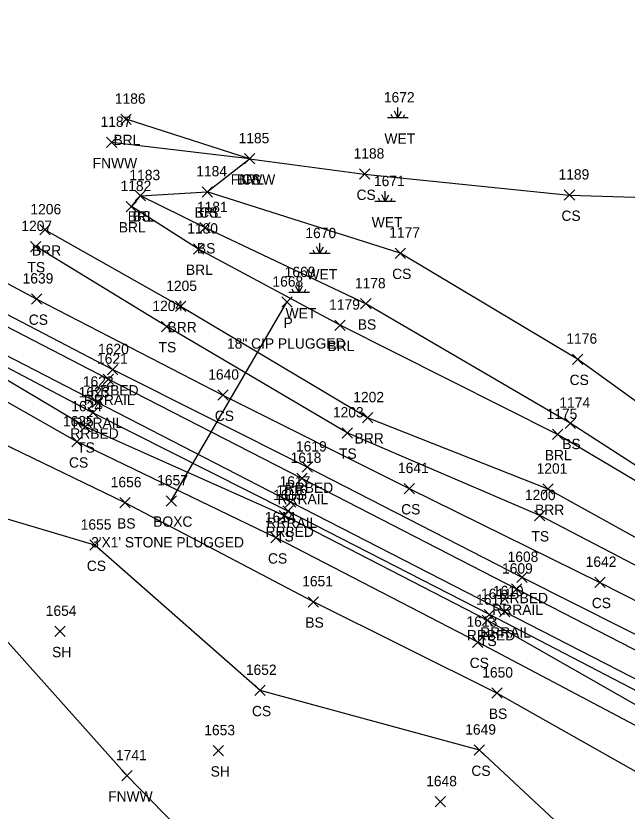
# Model space of a CAD drawing. Extents: x 1443960 to 1446865, y 610387 to 616706.
# Drawn here: x 1446375.4 to 1446493.6, y 611170.6 to 611324.5 of the extents above; entities that cross this region are included whole.
import ezdxf

# ---------------------------------------------------------------- set-up
doc = ezdxf.new("R2010")
doc.units = 0
for name, color, linetype in [('D_A', 7, 'Continuous'), ('D_C', 7, 'Continuous'), ('D_I', 7, 'Continuous'), ('D_TIC', 7, 'Continuous'), ('DCP', 7, 'Continuous'), ('L_A', 7, 'Continuous'), ('L_I', 7, 'Continuous'), ('L_TIC', 7, 'Continuous'), ('LABL', 7, 'Continuous'), ('LELB', 7, 'Continuous'), ('LFNC', 7, 'Continuous'), ('LWET', 7, 'Continuous'), ('R_A', 7, 'Continuous'), ('R_I', 7, 'Continuous'), ('R_TIC', 7, 'Continuous'), ('RR', 7, 'Continuous'), ('RRB', 7, 'Continuous')]:
    doc.layers.add(name, color=color, linetype=linetype)

msp = doc.modelspace()

# ---------------------------------------------------------------- linework, layer by layer
at = {"layer": 'D_TIC'}
for points in [[(1446426.77, 611268.12), (1446428.77, 611270.12)], [(1446428.77, 611268.12), (1446426.77, 611270.12)], [(1446404.42, 611229.65), (1446406.42, 611231.65)], [(1446406.42, 611229.65), (1446404.42, 611231.65)]]:
    msp.add_lwpolyline(points, dxfattribs=at)
at = {"layer": 'DCP'}
msp.add_lwpolyline([(1446405.42, 611230.65), (1446427.77, 611269.12)], dxfattribs=at)
at = {"layer": 'L_TIC'}
for points in [[(1446395.67, 611303.52), (1446397.67, 611305.52)], [(1446397.67, 611303.52), (1446395.67, 611305.52)], [(1446392.86, 611299.05), (1446394.86, 611301.05)], [(1446394.86, 611299.05), (1446392.86, 611301.05)], [(1446419.56, 611295.87), (1446421.56, 611297.87)], [(1446421.56, 611295.87), (1446419.56, 611297.87)], [(1446419.56, 611295.87), (1446421.56, 611297.87)], [(1446421.56, 611295.87), (1446419.56, 611297.87)], [(1446419.56, 611295.87), (1446421.56, 611297.87)], [(1446421.56, 611295.87), (1446419.56, 611297.87)], [(1446441.81, 611292.9), (1446443.81, 611294.9)], [(1446443.81, 611292.9), (1446441.81, 611294.9)], [(1446411.36, 611289.47), (1446413.36, 611291.47)], [(1446413.36, 611289.47), (1446411.36, 611291.47)], [(1446411.36, 611289.47), (1446413.36, 611291.47)], [(1446413.36, 611289.47), (1446411.36, 611291.47)], [(1446398.45, 611288.73), (1446400.45, 611290.73)], [(1446400.45, 611288.73), (1446398.45, 611290.73)], [(1446398.45, 611288.73), (1446400.45, 611290.73)], [(1446400.45, 611288.73), (1446398.45, 611290.73)], [(1446481.45, 611288.85), (1446483.45, 611290.85)], [(1446483.45, 611288.85), (1446481.45, 611290.85)], [(1446396.71, 611286.62), (1446398.71, 611288.62)], [(1446398.71, 611286.62), (1446396.71, 611288.62)], [(1446379.98, 611282.12), (1446381.98, 611284.12)], [(1446381.98, 611282.12), (1446379.98, 611284.12)], [(1446410.93, 611282.54), (1446412.93, 611284.54)], [(1446412.93, 611282.54), (1446410.93, 611284.54)], [(1446378.18, 611278.89), (1446380.18, 611280.89)], [(1446380.18, 611278.89), (1446378.18, 611280.89)], [(1446409.71, 611278.39), (1446411.71, 611280.39)], [(1446411.71, 611278.39), (1446409.71, 611280.39)], [(1446448.7, 611277.6), (1446450.7, 611279.6)], [(1446450.7, 611277.6), (1446448.7, 611279.6)], [(1446378.4, 611268.73), (1446380.4, 611270.73)], [(1446380.4, 611268.73), (1446378.4, 611270.73)], [(1446442.05, 611267.8), (1446444.05, 611269.8)], [(1446444.05, 611267.8), (1446442.05, 611269.8)], [(1446406.2, 611267.28), (1446408.2, 611269.28)], [(1446408.2, 611267.28), (1446406.2, 611269.28)], [(1446403.54, 611263.4), (1446405.54, 611265.4)], [(1446405.54, 611263.4), (1446403.54, 611265.4)], [(1446437.08, 611263.66), (1446439.08, 611265.66)], [(1446439.08, 611263.66), (1446437.08, 611265.66)], [(1446483.03, 611257.08), (1446485.03, 611259.08)], [(1446485.03, 611257.08), (1446483.03, 611259.08)], [(1446414.39, 611250.12), (1446416.39, 611252.12)], [(1446416.39, 611250.12), (1446414.39, 611252.12)], [(1446442.39, 611245.75), (1446444.39, 611247.75)], [(1446444.39, 611245.75), (1446442.39, 611247.75)], [(1446481.61, 611244.67), (1446483.61, 611246.67)], [(1446483.61, 611244.67), (1446481.61, 611246.67)], [(1446387.8, 611244), (1446389.8, 611246)], [(1446389.8, 611244), (1446387.8, 611246)], [(1446438.45, 611242.81), (1446440.45, 611244.81)], [(1446440.45, 611242.81), (1446438.45, 611244.81)], [(1446479.13, 611242.51), (1446481.13, 611244.51)], [(1446481.13, 611242.51), (1446479.13, 611244.51)], [(1446386.19, 611241.09), (1446388.19, 611243.09)], [(1446388.19, 611241.09), (1446386.19, 611243.09)], [(1446450.44, 611232.03), (1446452.44, 611234.03)], [(1446452.44, 611232.03), (1446450.44, 611234.03)], [(1446477.3, 611231.93), (1446479.3, 611233.93)], [(1446479.3, 611231.93), (1446477.3, 611233.93)], [(1446395.49, 611229.29), (1446397.49, 611231.29)], [(1446397.49, 611229.29), (1446395.49, 611231.29)], [(1446426.27, 611226.8), (1446428.27, 611228.8)], [(1446428.27, 611226.8), (1446426.27, 611228.8)], [(1446475.68, 611226.8), (1446477.68, 611228.8)], [(1446477.68, 611226.8), (1446475.68, 611228.8)], [(1446424.68, 611222.52), (1446426.68, 611224.52)], [(1446426.68, 611222.52), (1446424.68, 611224.52)], [(1446389.63, 611221.09), (1446391.63, 611223.09)], [(1446391.63, 611221.09), (1446389.63, 611223.09)], [(1446487.32, 611213.89), (1446489.32, 611215.89)], [(1446489.32, 611213.89), (1446487.32, 611215.89)], [(1446431.91, 611210.11), (1446433.91, 611212.11)], [(1446433.91, 611210.11), (1446431.91, 611212.11)], [(1446465.55, 611206.56), (1446467.55, 611208.56)], [(1446467.55, 611206.56), (1446465.55, 611208.56)], [(1446382.87, 611204.4), (1446384.87, 611206.4)], [(1446384.87, 611204.4), (1446382.87, 611206.4)], [(1446463.69, 611202.31), (1446465.69, 611204.31)], [(1446465.69, 611202.31), (1446463.69, 611204.31)], [(1446421.58, 611192.97), (1446423.58, 611194.97)], [(1446423.58, 611192.97), (1446421.58, 611194.97)], [(1446467.4, 611192.46), (1446469.4, 611194.46)], [(1446469.4, 611192.46), (1446467.4, 611194.46)], [(1446413.54, 611181.3), (1446415.54, 611183.3)], [(1446415.54, 611181.3), (1446413.54, 611183.3)], [(1446464.02, 611181.42), (1446466.02, 611183.42)], [(1446466.02, 611181.42), (1446464.02, 611183.42)], [(1446395.85, 611176.46), (1446397.85, 611178.46)], [(1446397.85, 611176.46), (1446395.85, 611178.46)], [(1446456.46, 611171.43), (1446458.46, 611173.43)], [(1446458.46, 611171.43), (1446456.46, 611173.43)]]:
    msp.add_lwpolyline(points, dxfattribs=at)
at = {"layer": 'LABL'}
for points in [[(1446517.97, 611221.87), (1446505.83, 611228.19), (1446480.13, 611243.51), (1446438.08, 611264.66), (1446410.71, 611279.39), (1446397.71, 611287.62), (1446399.45, 611289.73), (1446412.36, 611290.47), (1446420.56, 611296.87), (1446396.67, 611304.52)], [(1446517.97, 611221.87), (1446516.05, 611212), (1446478.3, 611232.93), (1446443.39, 611246.75), (1446407.2, 611268.28), (1446380.98, 611283.12)]]:
    msp.add_lwpolyline(points, dxfattribs=at)
at = {"layer": 'LELB'}
for points in [[(1446552.99, 611382.07), (1446558.67, 611362.69), (1446557.44, 611341.16), (1446560.67, 611304.99), (1446555.64, 611264.16), (1446556.53, 611215.55), (1446554.81, 611203.13), (1446541.6, 611207.37), (1446517.97, 611221.87), (1446506.75, 611230.08), (1446482.61, 611245.67), (1446443.05, 611268.8), (1446411.93, 611283.54), (1446399.45, 611289.73)], [(1446420.56, 611296.87), (1446442.81, 611293.9), (1446482.45, 611289.85), (1446511.86, 611288.91), (1446544.12, 611276.01)], [(1446554.81, 611203.13), (1446527.38, 611226.19), (1446501.38, 611245.5), (1446484.03, 611258.08), (1446449.7, 611278.6), (1446412.36, 611290.47)], [(1446344.24, 611288.47), (1446379.4, 611269.73), (1446415.39, 611251.12), (1446451.44, 611233.03), (1446488.32, 611214.89), (1446522.86, 611197.29), (1446554.41, 611180.54)], [(1446576.67, 611181), (1446566.72, 611186.09), (1446559.62, 611190.7), (1446541.15, 611196.83), (1446511.61, 611209.64), (1446476.68, 611227.8), (1446439.45, 611243.81), (1446404.54, 611264.4), (1446379.18, 611279.89)], [(1446548.85, 610888.19), (1446553.44, 610932.22), (1446554.61, 610954.43), (1446557.18, 610985.54), (1446561.83, 611026.07), (1446565.58, 611053.66), (1446570.69, 611096.92), (1446573.29, 611130.79), (1446568.51, 611145), (1446569.91, 611148.66), (1446564.88, 611156.7), (1446536.84, 611169.59), (1446508.69, 611183.48), (1446466.55, 611207.56), (1446427.27, 611227.8), (1446388.8, 611245), (1446349.69, 611268.25), (1446343.09, 611268.96)], [(1446552.43, 611156.81), (1446533.31, 611167.82), (1446507.38, 611180.73), (1446464.69, 611203.31), (1446425.68, 611223.52), (1446387.19, 611242.09), (1446349.13, 611263.69), (1446342.52, 611266.22)], [(1446545.33, 610990.77), (1446549.45, 611028.52), (1446549.03, 611055.59), (1446553.29, 611104.25), (1446542.01, 611115.66), (1446540.05, 611127.24), (1446544.04, 611129.96), (1446551.51, 611136.49), (1446553.27, 611138.91), (1446550.53, 611149.51), (1446533.12, 611159.93), (1446498.33, 611176.52), (1446468.4, 611193.46), (1446432.91, 611211.11), (1446396.49, 611230.29), (1446366.67, 611244.64), (1446348.43, 611256.48)], [(1446530.86, 610991.05), (1446536.61, 611027.8), (1446530.46, 611055.9), (1446528.01, 611097.29), (1446529.9, 611126.45), (1446531.13, 611139.44), (1446489.18, 611159.91), (1446465.02, 611182.42), (1446422.58, 611193.97), (1446390.63, 611222.09), (1446361.12, 611230.87), (1446345.74, 611242.49)]]:
    msp.add_lwpolyline(points, dxfattribs=at)
at = {"layer": 'LFNC'}
for points in [[(1446420.56, 611296.87), (1446393.86, 611300.05)], [(1446365.2, 611212.86), (1446396.85, 611177.46)], [(1446487.06, 611083.87), (1446458.93, 611112.28), (1446429.85, 611143.59), (1446396.85, 611177.46)]]:
    msp.add_lwpolyline(points, dxfattribs=at)
at = {"layer": 'LWET'}
for p, q in [((1446449.27, 611304.78), (1446449.27, 611306.78)), ((1446448.27, 611304.78), (1446447.94, 611305.44)), ((1446449.27, 611304.78), (1446448.61, 611306.11)), ((1446449.27, 611304.78), (1446449.94, 611306.11)), ((1446450.27, 611304.78), (1446450.61, 611305.44)), ((1446451.27, 611304.78), (1446447.27, 611304.78)), ((1446446.81, 611288.57), (1446446.14, 611289.9)), ((1446446.81, 611288.57), (1446446.81, 611290.57)), ((1446446.81, 611288.57), (1446447.47, 611289.9)), ((1446448.81, 611288.57), (1446444.81, 611288.57)), ((1446445.81, 611288.57), (1446445.47, 611289.23)), ((1446447.81, 611288.57), (1446448.14, 611289.23)), ((1446434.18, 611278.51), (1446434.18, 611280.51)), ((1446433.18, 611278.51), (1446432.85, 611279.17)), ((1446434.18, 611278.51), (1446433.52, 611279.84)), ((1446434.18, 611278.51), (1446434.85, 611279.84)), ((1446435.18, 611278.51), (1446435.52, 611279.17)), ((1446436.18, 611278.51), (1446432.18, 611278.51)), ((1446430.14, 611270.98), (1446430.14, 611272.98)), ((1446429.14, 611270.98), (1446428.81, 611271.65)), ((1446430.14, 611270.98), (1446429.47, 611272.31)), ((1446430.14, 611270.98), (1446430.81, 611272.31)), ((1446431.14, 611270.98), (1446431.47, 611271.65)), ((1446432.14, 611270.98), (1446428.14, 611270.98))]:
    msp.add_line(p, q, dxfattribs=at)
at = {"layer": 'R_TIC'}
for points in [[(1446393.07, 611255.06), (1446395.07, 611257.06)], [(1446395.07, 611255.06), (1446393.07, 611257.06)], [(1446392.22, 611253.19), (1446394.22, 611255.19)], [(1446394.22, 611253.19), (1446392.22, 611255.19)], [(1446390.04, 611248.76), (1446392.04, 611250.76)], [(1446392.04, 611248.76), (1446390.04, 611250.76)], [(1446389.24, 611246.7), (1446391.24, 611248.7)], [(1446391.24, 611246.7), (1446389.24, 611248.7)], [(1446430.72, 611236.21), (1446432.72, 611238.21)], [(1446432.72, 611236.21), (1446430.72, 611238.21)], [(1446429.68, 611234.02), (1446431.68, 611236.02)], [(1446431.68, 611234.02), (1446429.68, 611236.02)], [(1446427.54, 611229.42), (1446429.54, 611231.42)], [(1446429.54, 611229.42), (1446427.54, 611231.42)], [(1446426.98, 611227.69), (1446428.98, 611229.69)], [(1446428.98, 611227.69), (1446426.98, 611229.69)], [(1446472.29, 611214.85), (1446474.29, 611216.85)], [(1446474.29, 611214.85), (1446472.29, 611216.85)], [(1446471.23, 611212.59), (1446473.23, 611214.59)], [(1446473.23, 611212.59), (1446471.23, 611214.59)], [(1446465.95, 611207.66), (1446467.95, 611209.66)], [(1446467.95, 611207.66), (1446465.95, 611209.66)], [(1446468.88, 611208.21), (1446470.88, 611210.21)], [(1446470.88, 611208.21), (1446468.88, 611210.21)]]:
    msp.add_lwpolyline(points, dxfattribs=at)
at = {"layer": 'RR'}
for points in [[(1446830.8, 611028.51), (1446813.8, 611037.34), (1446780.13, 611054.63), (1446766.6, 611061.72), (1446723.16, 611084.18), (1446681.83, 611105.5), (1446667.65, 611112.72), (1446650.45, 611121.75), (1446635.82, 611129.05), (1446620.36, 611137.27), (1446611.04, 611142.08), (1446598.97, 611148.35), (1446587.47, 611154.32), (1446577.27, 611159.61), (1446545.1, 611176.06), (1446537.95, 611179.67), (1446530.32, 611183.72), (1446472.23, 611213.59), (1446430.68, 611235.02), (1446393.22, 611254.19), (1446353.39, 611274.79), (1446345.67, 611278.8)], [(1446830.61, 611022.91), (1446812, 611032.72), (1446777.67, 611050.48), (1446764.9, 611057.05), (1446720.8, 611079.76), (1446679.61, 611101.04), (1446672.6, 611104.75), (1446648.09, 611117.4), (1446634.05, 611124.73), (1446619.04, 611132.42), (1446610.71, 611136.75), (1446598.39, 611142.94), (1446586.96, 611148.93), (1446576.92, 611154.08), (1446541.41, 611172.48), (1446511.36, 611187.89), (1446469.88, 611209.21), (1446428.54, 611230.42), (1446391.04, 611249.76), (1446351.07, 611270.34), (1446343.04, 611274.54)]]:
    msp.add_lwpolyline(points, dxfattribs=at)
at = {"layer": 'RRB'}
for points in [[(1446569.99, 611168.04), (1446545.96, 611178.46), (1446513.02, 611195.82), (1446473.29, 611215.85), (1446431.72, 611237.21), (1446394.07, 611256.06), (1446354.34, 611276.82), (1446346.71, 611281.18)], [(1446564.88, 611156.7), (1446537.51, 611171.94), (1446510.38, 611186.08), (1446466.95, 611208.66), (1446427.98, 611228.69), (1446390.24, 611247.7), (1446350.09, 611268.94), (1446342.68, 611272.23)]]:
    msp.add_lwpolyline(points, dxfattribs=at)

# ---------------------------------------------------------------- texts
at = {"layer": 'D_A'}
for s, p in [('P', (1446427.14, 611264.12)), ('BOXC', (1446401.92, 611225.65))]:
    msp.add_text(s, height=2, dxfattribs=at).set_placement(p)
at = {"layer": 'D_C'}
for s, p in [('18" CIP PLUGGED', (1446416.18, 611260.12)), ("3'X1' STONE PLUGGED", (1446389.92, 611221.65))]:
    msp.add_text(s, height=2, dxfattribs=at).set_placement(p)
at = {"layer": 'D_I'}
for s, p in [('1668', (1446424.98, 611272.12)), ('1657', (1446402.68, 611233.65))]:
    msp.add_text(s, height=2, dxfattribs=at).set_placement(p)
at = {"layer": 'L_A'}
for s, p in [('BRL', (1446394.22, 611299.52)), ('WET', (1446446.65, 611299.78)), ('FNWW', (1446390.2, 611295.05)), ('FNWW', (1446416.91, 611291.87)), ('BRL', (1446418.1, 611291.87)), ('CS', (1446419, 611291.87)), ('CS', (1446441.25, 611288.9)), ('BRL', (1446396.99, 611284.73)), ('BS', (1446397.89, 611284.73)), ('BRL', (1446409.91, 611285.47)), ('CS', (1446410.81, 611285.47)), ('CS', (1446480.89, 611284.85)), ('WET', (1446444.19, 611283.57)), ('BRL', (1446395.25, 611282.62)), ('BS', (1446410.37, 611278.54)), ('BRR', (1446378.47, 611278.12)), ('TS', (1446377.59, 611274.89)), ('BRL', (1446408.25, 611274.39)), ('WET', (1446431.56, 611273.51)), ('CS', (1446448.14, 611273.6)), ('CS', (1446377.84, 611264.73)), ('WET', (1446427.52, 611265.98)), ('BRR', (1446404.69, 611263.28)), ('BS', (1446441.49, 611263.8)), ('TS', (1446402.95, 611259.4)), ('BRL', (1446435.62, 611259.66)), ('CS', (1446482.47, 611253.08)), ('CS', (1446413.83, 611246.12)), ('BRR', (1446440.88, 611241.75)), ('TS', (1446387.21, 611240)), ('BS', (1446481.05, 611240.67)), ('TS', (1446437.86, 611238.81)), ('BRL', (1446477.67, 611238.51)), ('CS', (1446385.63, 611237.09)), ('CS', (1446449.88, 611228.03)), ('BRR', (1446475.79, 611227.93)), ('BS', (1446394.93, 611225.29)), ('TS', (1446425.68, 611222.8)), ('TS', (1446475.09, 611222.8)), ('CS', (1446424.12, 611218.52)), ('CS', (1446389.07, 611217.09)), ('CS', (1446486.76, 611209.89)), ('BS', (1446431.35, 611206.11)), ('TS', (1446464.96, 611202.56)), ('SH', (1446382.36, 611200.4)), ('CS', (1446463.14, 611198.31)), ('CS', (1446421.02, 611188.97)), ('BS', (1446466.84, 611188.46)), ('SH', (1446413.03, 611177.3)), ('CS', (1446463.47, 611177.42)), ('FNWW', (1446393.2, 611172.46))]:
    msp.add_text(s, height=2, dxfattribs=at).set_placement(p)
at = {"layer": 'L_I'}
for s, p in [('1672', (1446446.53, 611307.78)), ('1186', (1446394.49, 611307.52)), ('1187', (1446391.73, 611303.05)), ('1185', (1446418.43, 611299.87)), ('1185', (1446418.43, 611299.87)), ('1185', (1446418.43, 611299.87)), ('1188', (1446440.68, 611296.9)), ('1183', (1446397.32, 611292.73)), ('1183', (1446397.32, 611292.73)), ('1184', (1446410.24, 611293.47)), ('1184', (1446410.24, 611293.47)), ('1189', (1446480.32, 611292.85)), ('1671', (1446444.63, 611291.57)), ('1182', (1446395.59, 611290.62)), ('1206', (1446378.16, 611286.12)), ('1181', (1446410.37, 611286.54)), ('1207', (1446376.41, 611282.89)), ('1180', (1446408.49, 611282.39)), ('1670', (1446431.36, 611281.51)), ('1177', (1446447.57, 611281.6)), ('1669', (1446427.35, 611273.98)), ('1639', (1446376.65, 611272.73)), ('1205', (1446404.43, 611271.28)), ('1178', (1446440.93, 611271.8)), ('1179', (1446435.95, 611267.66)), ('1204', (1446401.77, 611267.4)), ('1176', (1446481.85, 611261.08)), ('1640', (1446412.56, 611254.12)), ('1202', (1446440.62, 611249.75)), ('1624', (1446386.06, 611248)), ('1174', (1446480.49, 611248.67)), ('1203', (1446436.68, 611246.81)), ('1175', (1446478.01, 611246.51)), ('1625', (1446384.45, 611245.09)), ('1641', (1446449.27, 611236.03)), ('1201', (1446476.09, 611235.93)), ('1656', (1446393.7, 611233.29)), ('1615', (1446425.1, 611230.8)), ('1200', (1446473.82, 611230.8)), ('1614', (1446423.51, 611226.52)), ('1655', (1446387.89, 611225.09)), ('1642', (1446485.58, 611217.89)), ('1651', (1446430.74, 611214.11)), ('1612', (1446464.38, 611210.56)), ('1654', (1446381.13, 611208.4)), ('1613', (1446462.52, 611206.31)), ('1652', (1446419.84, 611196.97)), ('1650', (1446465.57, 611196.46)), ('1653', (1446411.8, 611185.3)), ('1649', (1446462.28, 611185.42)), ('1741', (1446394.72, 611180.46)), ('1648', (1446454.72, 611175.43))]:
    msp.add_text(s, height=2, dxfattribs=at).set_placement(p)
at = {"layer": 'R_A'}
for s, p in [('RRBED', (1446389.72, 611251.06)), ('RRRAIL', (1446388.52, 611249.19)), ('RRRAIL', (1446386.33, 611244.76)), ('RRBED', (1446385.88, 611242.7)), ('RRBED', (1446427.37, 611232.21)), ('RRRAIL', (1446425.97, 611230.02)), ('RRRAIL', (1446423.83, 611225.42)), ('RRBED', (1446423.63, 611223.69)), ('RRBED', (1446468.93, 611210.85)), ('RRRAIL', (1446467.52, 611208.59)), ('RRBED', (1446462.59, 611203.66)), ('RRRAIL', (1446465.17, 611204.21))]:
    msp.add_text(s, height=2, dxfattribs=at).set_placement(p)
at = {"layer": 'R_I'}
for s, p in [('1620', (1446391.25, 611259.06)), ('1621', (1446391.05, 611257.19)), ('1622', (1446388.3, 611252.76)), ('1623', (1446387.5, 611250.7)), ('1619', (1446429.54, 611240.21)), ('1618', (1446428.5, 611238.02)), ('1617', (1446426.36, 611233.42)), ('1616', (1446425.75, 611231.69)), ('1608', (1446470.47, 611218.85)), ('1609', (1446469.4, 611216.59)), ('1611', (1446465.34, 611211.66)), ('1610', (1446467.62, 611212.21))]:
    msp.add_text(s, height=2, dxfattribs=at).set_placement(p)

doc.saveas('drawing.dxf')
